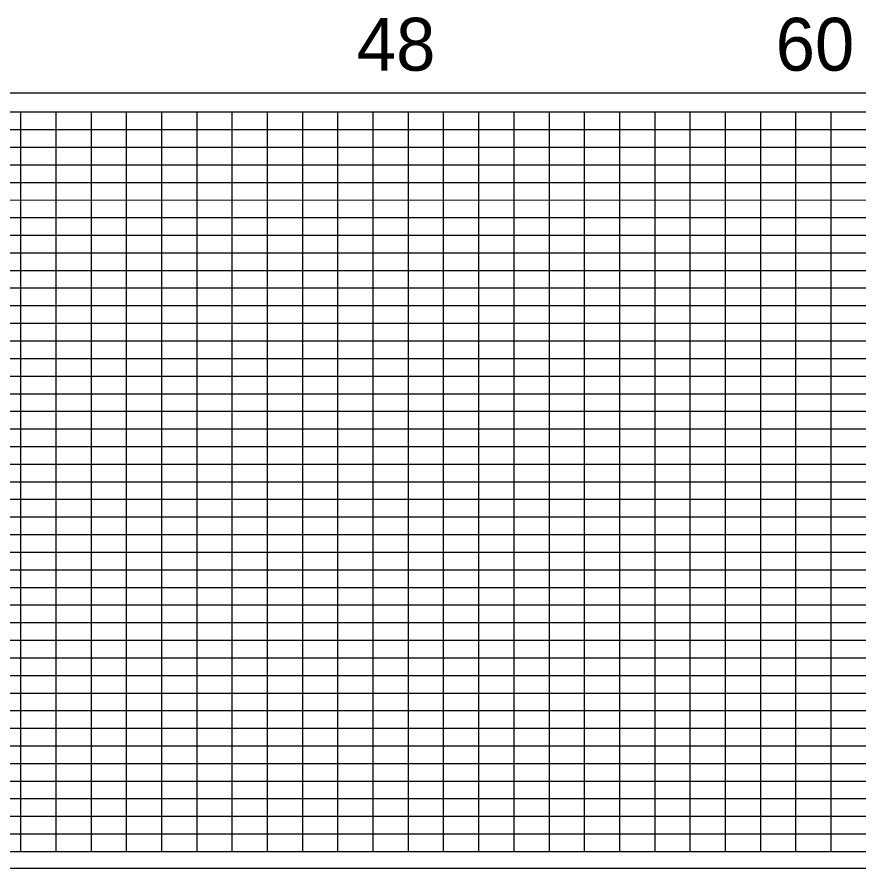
# Model space of a CAD drawing. Extents: x 1894907 to 1905782, y 740939 to 777025.
# Drawn here: x 1896926 to 1898121, y 775566 to 776774 of the extents above; entities that cross this region are included whole.
import ezdxf

# ---------------------------------------------------------------- set-up
doc = ezdxf.new("R2010")
doc.units = 0
doc.layers.add('RD_PD_WallFill', color=7, linetype='Continuous')
doc.layers.add('RD_SHT_IplotShp', color=7, linetype='Continuous')

msp = doc.modelspace()

# ---------------------------------------------------------------- linework, layer by layer
at = {"layer": 'RD_PD_WallFill'}
for p, q in [((1895081.6, 776639.1), (1900431.6, 776639.1)), ((1896931.6, 775589.1), (1896931.6, 776639.1)), ((1896981.6, 775589.1), (1896981.6, 776639.1)), ((1897031.6, 775589.1), (1897031.6, 776639.1)), ((1897081.6, 775589.1), (1897081.6, 776639.1)), ((1897131.6, 775589.1), (1897131.6, 776639.1)), ((1897181.6, 775589.1), (1897181.6, 776639.1)), ((1897231.6, 775589.1), (1897231.6, 776639.1)), ((1897281.6, 775589.1), (1897281.6, 776639.1)), ((1897331.6, 775589.1), (1897331.6, 776639.1)), ((1897381.6, 775589.1), (1897381.6, 776639.1)), ((1897431.6, 775589.1), (1897431.6, 776639.1)), ((1897481.6, 775589.1), (1897481.6, 776639.1)), ((1897531.6, 775589.1), (1897531.6, 776639.1)), ((1897581.6, 775589.1), (1897581.6, 776639.1)), ((1897631.6, 775589.1), (1897631.6, 776639.1)), ((1897681.6, 775589.1), (1897681.6, 776639.1)), ((1897731.6, 775589.1), (1897731.6, 776639.1)), ((1897781.6, 775589.1), (1897781.6, 776639.1)), ((1897831.6, 775589.1), (1897831.6, 776639.1)), ((1897881.6, 775589.1), (1897881.6, 776639.1)), ((1897931.6, 775589.1), (1897931.6, 776639.1)), ((1897981.6, 775589.1), (1897981.6, 776639.1)), ((1898031.6, 775589.1), (1898031.6, 776639.1)), ((1898081.6, 775589.1), (1898081.6, 776639.1)), ((1895531.6, 776614.1), (1900431.6, 776614.1)), ((1895531.6, 776589.1), (1900431.6, 776589.1)), ((1895531.6, 776564.1), (1900431.6, 776564.1)), ((1895531.6, 776539.2), (1900431.6, 776539.1)), ((1895531.6, 776514.1), (1900431.6, 776514.2)), ((1895081.6, 776489.1), (1900431.6, 776489.1)), ((1895081.6, 776464.1), (1900431.6, 776464.1)), ((1895081.6, 776439.1), (1900431.6, 776439.2)), ((1895081.6, 776414.2), (1900431.6, 776414.1)), ((1895081.6, 776389.2), (1900431.6, 776389.2)), ((1895081.6, 776364.1), (1900431.6, 776364.1)), ((1895081.6, 776339.1), (1900431.6, 776339.1)), ((1895081.6, 776314.2), (1900431.6, 776314.1)), ((1895081.6, 776289.1), (1900431.6, 776289.1)), ((1895081.6, 776264.2), (1900431.6, 776264.1)), ((1895081.6, 776239.1), (1900431.6, 776239.1)), ((1895081.6, 776214.1), (1900431.6, 776214.2)), ((1895081.6, 776189.1), (1900431.6, 776189.1)), ((1895081.6, 776164.1), (1900431.6, 776164.2)), ((1895081.6, 776139.1), (1900431.6, 776139.1)), ((1895081.6, 776114.1), (1900431.6, 776114.1)), ((1895081.6, 776089.2), (1900431.6, 776089.1)), ((1895081.6, 776064.1), (1900431.6, 776064.1)), ((1895081.6, 776039.1), (1900431.6, 776039.1)), ((1895081.6, 776014.1), (1900431.6, 776014.1)), ((1895081.6, 775989.1), (1900431.6, 775989.2)), ((1895081.6, 775964.1), (1900431.6, 775964.1)), ((1895081.6, 775939.1), (1900431.6, 775939.1)), ((1895081.6, 775914.1), (1900431.6, 775914.1)), ((1895081.6, 775889.1), (1900431.6, 775889.1)), ((1895081.6, 775864.1), (1900431.6, 775864.1)), ((1895081.6, 775839.1), (1900431.6, 775839.1)), ((1895081.6, 775814.1), (1900431.6, 775814.1)), ((1895081.6, 775789.1), (1900431.6, 775789.1)), ((1895081.6, 775764.1), (1900431.6, 775764.1)), ((1895081.6, 775739.1), (1900431.6, 775739.1)), ((1895081.6, 775714.1), (1900431.6, 775714.1)), ((1895081.6, 775689.1), (1900431.6, 775689.1)), ((1895081.6, 775664.1), (1900431.6, 775664.1)), ((1895081.6, 775639.1), (1900431.6, 775639.1)), ((1895131.6, 775614.1), (1900431.6, 775614.1)), ((1895081.6, 775589.1), (1900431.6, 775589.1))]:
    msp.add_line(p, q, dxfattribs=at)
at = {"layer": 'RD_SHT_IplotShp'}
msp.add_lwpolyline([(1895056.6, 775565.6), (1900456.6, 775565.6), (1900456.6, 776665.6), (1895056.6, 776665.6)], close=True, dxfattribs=at)

# ---------------------------------------------------------------- texts
at = {"layer": 'RD_PD_WallFill'}
for s, p in [('48', (1897408.3, 776697.8)), ('60', (1898002.8, 776697.8))]:
    msp.add_text(s, height=75, dxfattribs=at).set_placement(p)

doc.saveas('drawing.dxf')
